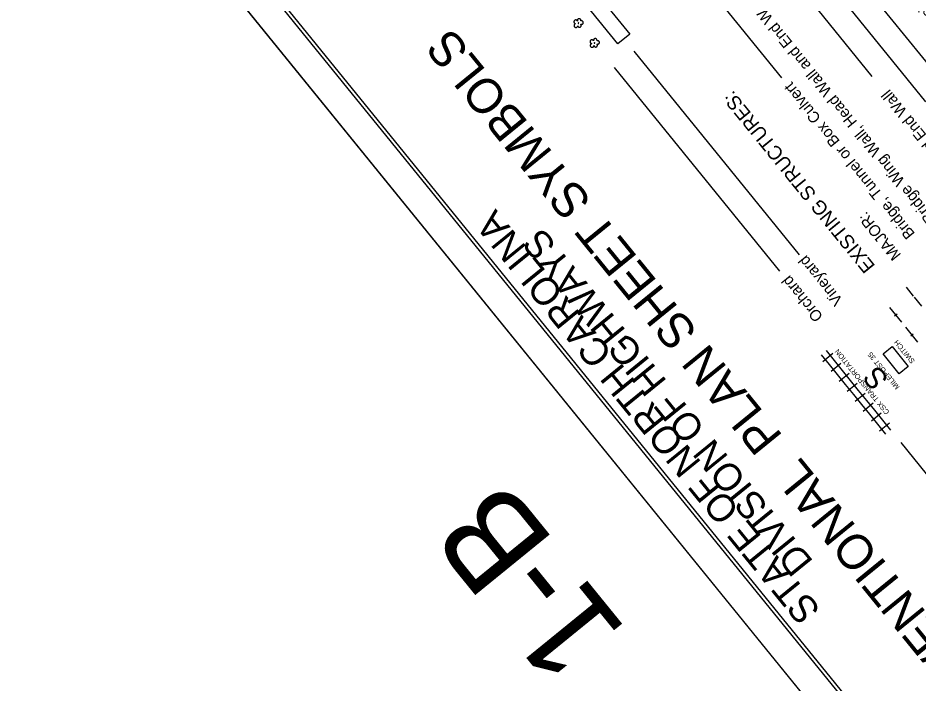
# Model space of a CAD drawing. Extents: x 2596486 to 2602076, y 851390 to 856110.
# Drawn here: x 2598780 to 2599484, y 854669 to 855189 of the extents above; entities that cross this region are included whole.
import ezdxf

# ---------------------------------------------------------------- set-up
doc = ezdxf.new("R2010")
doc.units = 0
for name, color, linetype in [('Default', 7, 'Continuous'), ('Sheet Cutting Line CELL', 7, 'Continuous'), ('Sheet Plot Border Inside CELL', 7, 'Continuous'), ('Sheet Plot Border Outside CELL', 7, 'Continuous'), ('Sheet Symbology CELL', 7, 'Continuous')]:
    doc.layers.add(name, color=color, linetype=linetype)

msp = doc.modelspace()

# ---------------------------------------------------------------- linework, layer by layer
at = {"layer": 'Sheet Cutting Line CELL'}
msp.add_line((2598780.26, 855415.74), (2599842.38, 854108.93), dxfattribs=at)
at = {"layer": 'Sheet Plot Border Inside CELL'}
msp.add_lwpolyline([(2600670.38, 854798.64), (2599619.29, 856091.87), (2598800.52, 855426.4), (2599851.6, 854133.17)], close=True, dxfattribs=at)
at = {"layer": 'Sheet Plot Border Outside CELL'}
msp.add_lwpolyline([(2600696, 854802.71), (2599633.88, 856109.52), (2598780.26, 855415.74), (2599842.38, 854108.93)], close=True, dxfattribs=at)
at = {"layer": 'Sheet Symbology CELL'}
for p, q in [((2599397.87, 855268.25), (2599513.59, 855125.87)), ((2599382.35, 855255.63), (2599489.69, 855123.56)), ((2599366.83, 855243.02), (2599447.75, 855143.46)), ((2599323.71, 855207.97), (2599376.95, 855142.46)), ((2599261.65, 855163.09), (2599390.9, 855004.06)), ((2599246.13, 855150.48), (2599375.38, 854991.44)), ((2599480.32, 854971.84), (2599474.64, 854978.83)), ((2599486.62, 854964.08), (2599480.95, 854971.07)), ((2599471.1, 854951.47), (2599461.64, 854963.11)), ((2599465.4, 854956.5), (2599467.34, 854958.08)), ((2599483.72, 854935.95), (2599474.26, 854947.59)), ((2599478.02, 854940.98), (2599479.96, 854942.56)), ((2599418.42, 854921.54), (2599412.11, 854929.3)), ((2599414.54, 854918.38), (2599408.23, 854926.14)), ((2599417.21, 854926.99), (2599409.45, 854920.69)), ((2599424.73, 854913.78), (2599418.42, 854921.54)), ((2599420.85, 854910.62), (2599414.54, 854918.38)), ((2599423.51, 854919.23), (2599415.75, 854912.93)), ((2599431.03, 854906.02), (2599424.73, 854913.78)), ((2599427.15, 854902.86), (2599420.85, 854910.62)), ((2599429.82, 854911.47), (2599422.06, 854905.17)), ((2599433.46, 854895.1), (2599427.15, 854902.86)), ((2599436.13, 854903.71), (2599428.37, 854897.41)), ((2599437.34, 854898.26), (2599431.03, 854906.02)), ((2599439.77, 854887.34), (2599433.46, 854895.1)), ((2599442.44, 854895.95), (2599434.68, 854889.65)), ((2599443.65, 854890.5), (2599437.34, 854898.26)), ((2599446.08, 854879.58), (2599439.77, 854887.34)), ((2599448.74, 854888.19), (2599440.98, 854881.89)), ((2599449.96, 854882.74), (2599443.65, 854890.5)), ((2599452.38, 854871.82), (2599446.08, 854879.58)), ((2599455.05, 854880.43), (2599447.29, 854874.13)), ((2599456.26, 854874.98), (2599449.96, 854882.74)), ((2599458.69, 854864.06), (2599452.38, 854871.82)), ((2599461.36, 854872.67), (2599453.6, 854866.37)), ((2599462.57, 854867.22), (2599456.26, 854874.98)), ((2599470.2, 854857.45), (2599570.12, 854734.52))]:
    msp.add_line(p, q, dxfattribs=at)
for points in [[(2598810.38, 855418.31), (2599756.45, 854254.29), (2600570.48, 854915.9), (2599624.41, 856079.92)], [(2599469.1, 854911.18), (2599456.49, 854926.7), (2599463.55, 854932.44), (2599476.16, 854916.92)]]:
    msp.add_lwpolyline(points, close=True, dxfattribs=at)
for points in [[(2599249.17, 855168.92), (2599198.72, 855231.01), (2599208.03, 855238.57), (2599258.49, 855176.49), (2599249.17, 855168.92)], [(2599220.31, 855186.83), (2599220.21, 855187.52), (2599220.1, 855187.82), (2599219.95, 855188.08), (2599219.72, 855188.28), (2599219.48, 855188.41), (2599219.21, 855188.51), (2599218.9, 855188.58), (2599218.61, 855188.54), (2599218.35, 855188.46), (2599218.05, 855188.35), (2599217.85, 855188.12), (2599217.65, 855187.89), (2599217.54, 855187.55), (2599217.48, 855187.3), (2599217.53, 855187.02), (2599217.6, 855186.69), (2599217.45, 855186.95), (2599217.23, 855187.22), (2599216.99, 855187.35), (2599216.69, 855187.49), (2599216.41, 855187.59), (2599216.09, 855187.59), (2599215.76, 855187.52), (2599215.5, 855187.37), (2599215.24, 855187.22), (2599215.03, 855186.99), (2599214.87, 855186.72), (2599214.8, 855186.41), (2599214.76, 855186.06), (2599214.8, 855185.77), (2599214.91, 855185.47), (2599215.06, 855185.21), (2599215.25, 855184.98), (2599215.52, 855184.81), (2599215.79, 855184.71), (2599216.11, 855184.64)], [(2599216.11, 855184.64), (2599215.78, 855184.57), (2599215.52, 855184.41), (2599215.31, 855184.19), (2599215.11, 855183.96), (2599215.01, 855183.68), (2599214.91, 855183.41), (2599214.92, 855183.09), (2599214.96, 855182.8), (2599215.1, 855182.47), (2599215.26, 855182.27), (2599215.49, 855182.07), (2599215.75, 855181.9), (2599216.03, 855181.8), (2599216.34, 855181.74), (2599216.67, 855181.81), (2599216.92, 855181.89), (2599217.19, 855182.04), (2599217.42, 855182.23), (2599217.62, 855182.46), (2599217.72, 855182.73), (2599217.83, 855183.07), (2599217.87, 855182.79), (2599218.02, 855182.52), (2599218.21, 855182.29), (2599218.45, 855182.16), (2599218.68, 855182.03), (2599218.99, 855181.96), (2599219.28, 855181.93), (2599219.56, 855181.97), (2599219.79, 855182.09), (2599220.09, 855182.27), (2599220.25, 855182.47), (2599220.39, 855182.7), (2599220.45, 855183.02), (2599220.51, 855183.26), (2599220.47, 855183.55), (2599220.4, 855183.87), (2599220.28, 855184.1), (2599220.09, 855184.33), (2599220.33, 855184.2), (2599220.64, 855184.13), (2599220.89, 855184.14), (2599221.19, 855184.26), (2599221.48, 855184.37), (2599221.68, 855184.53), (2599221.88, 855184.75), (2599221.98, 855185.03), (2599222.08, 855185.3), (2599222.1, 855185.58), (2599222.06, 855185.87), (2599221.98, 855186.13), (2599221.79, 855186.36), (2599221.61, 855186.59), (2599221.41, 855186.76), (2599221.1, 855186.82), (2599220.82, 855186.92), (2599220.31, 855186.83)], [(2599218, 855185.08), (2599218.1, 855184.97), (2599218.2, 855184.92), (2599218.3, 855184.87), (2599218.42, 855184.97), (2599218.49, 855185.03), (2599218.51, 855185.17), (2599218.41, 855185.29), (2599218.35, 855185.37), (2599218.21, 855185.38), (2599218.06, 855185.32), (2599218.02, 855185.22), (2599218, 855185.08)], [(2599232.93, 855171.31), (2599232.82, 855172), (2599232.71, 855172.3), (2599232.56, 855172.56), (2599232.33, 855172.76), (2599232.1, 855172.89), (2599231.82, 855172.99), (2599231.51, 855173.06), (2599231.22, 855173.02), (2599230.96, 855172.94), (2599230.67, 855172.83), (2599230.47, 855172.6), (2599230.27, 855172.37), (2599230.16, 855172.03), (2599230.1, 855171.78), (2599230.14, 855171.49), (2599230.21, 855171.17), (2599230.06, 855171.43), (2599229.84, 855171.7), (2599229.61, 855171.83), (2599229.3, 855171.97), (2599229.03, 855172.07), (2599228.71, 855172.07), (2599228.38, 855172), (2599228.11, 855171.85), (2599227.85, 855171.7), (2599227.65, 855171.47), (2599227.48, 855171.2), (2599227.41, 855170.89), (2599227.38, 855170.54), (2599227.42, 855170.25), (2599227.53, 855169.95), (2599227.68, 855169.69), (2599227.87, 855169.45), (2599228.13, 855169.29), (2599228.41, 855169.19), (2599228.72, 855169.12)], [(2599228.72, 855169.12), (2599228.39, 855169.05), (2599228.13, 855168.89), (2599227.93, 855168.67), (2599227.73, 855168.44), (2599227.63, 855168.16), (2599227.53, 855167.89), (2599227.53, 855167.57), (2599227.57, 855167.28), (2599227.72, 855166.95), (2599227.87, 855166.75), (2599228.1, 855166.55), (2599228.37, 855166.38), (2599228.64, 855166.28), (2599228.95, 855166.21), (2599229.28, 855166.29), (2599229.54, 855166.37), (2599229.8, 855166.52), (2599230.04, 855166.71), (2599230.24, 855166.94), (2599230.34, 855167.21), (2599230.44, 855167.55), (2599230.48, 855167.27), (2599230.64, 855167), (2599230.82, 855166.77), (2599231.06, 855166.64), (2599231.3, 855166.51), (2599231.61, 855166.44), (2599231.89, 855166.41), (2599232.18, 855166.45), (2599232.4, 855166.57), (2599232.71, 855166.75), (2599232.87, 855166.95), (2599233, 855167.18), (2599233.07, 855167.5), (2599233.13, 855167.74), (2599233.09, 855168.03), (2599233.01, 855168.35), (2599232.9, 855168.58), (2599232.71, 855168.81), (2599232.94, 855168.68), (2599233.25, 855168.61), (2599233.5, 855168.62), (2599233.8, 855168.74), (2599234.1, 855168.85), (2599234.29, 855169), (2599234.49, 855169.23), (2599234.59, 855169.51), (2599234.69, 855169.78), (2599234.72, 855170.06), (2599234.68, 855170.35), (2599234.6, 855170.61), (2599234.41, 855170.84), (2599234.22, 855171.07), (2599234.02, 855171.24), (2599233.71, 855171.3), (2599233.44, 855171.4), (2599232.93, 855171.31)], [(2599230.62, 855169.56), (2599230.71, 855169.45), (2599230.81, 855169.4), (2599230.91, 855169.35), (2599231.03, 855169.45), (2599231.11, 855169.51), (2599231.12, 855169.65), (2599231.03, 855169.77), (2599230.96, 855169.85), (2599230.82, 855169.86), (2599230.68, 855169.8), (2599230.63, 855169.7), (2599230.62, 855169.56)]]:
    msp.add_lwpolyline(points, dxfattribs=at)

# ---------------------------------------------------------------- texts
at = {"layer": 'Default'}
msp.add_text('1-B', height=75, rotation=129.10281, dxfattribs=at).set_placement((2599257.28, 854710.14))
at = {"layer": 'Sheet Symbology CELL'}
for s, height, p in [('Drainage Box: Catch Basin, DI or JB', 8.75, (2599574.84, 855096.43)), ('Bridge Wing Wall, Head Wall and End Wall', 8.75, (2599497.26, 855033.36)), ('CONVENTIONAL  PLAN SHEET SYMBOLS', 27.2003, (2599572.48, 854624.06)), ('Bridge, Tunnel or Box Culvert', 8.75, (2599481.74, 855020.75)), ('EXISTING STRUCTURES:', 11, (2599450.7, 854995.52)), ('Head and End Wall', 8.75, (2599524.86, 855055.79)), ('STATE OF NORTH CAROLINA', 21.419, (2599408.36, 854726.9)), ('MAJOR:', 8.75, (2599470.88, 855004.16)), ('DIVISION OF HIGHWAYS', 21.419, (2599402.52, 854764.48)), ('Vineyard', 8.75, (2599425.46, 854968.71)), ('Orchard', 8.75, (2599409.94, 854956.1)), ('SWITCH', 4, (2599481.56, 854921.24)), ('CSX TRANSPORTATION', 4, (2599461.67, 854881.38)), ('MILEPOST 35', 4, (2599469.66, 854901.01)), ('S', 16.5, (2599461.46, 854907.25))]:
    msp.add_text(s, height=height, rotation=129.10281, dxfattribs=at).set_placement(p)

doc.saveas('drawing.dxf')
